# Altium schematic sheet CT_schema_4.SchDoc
size 313 x 185 mm
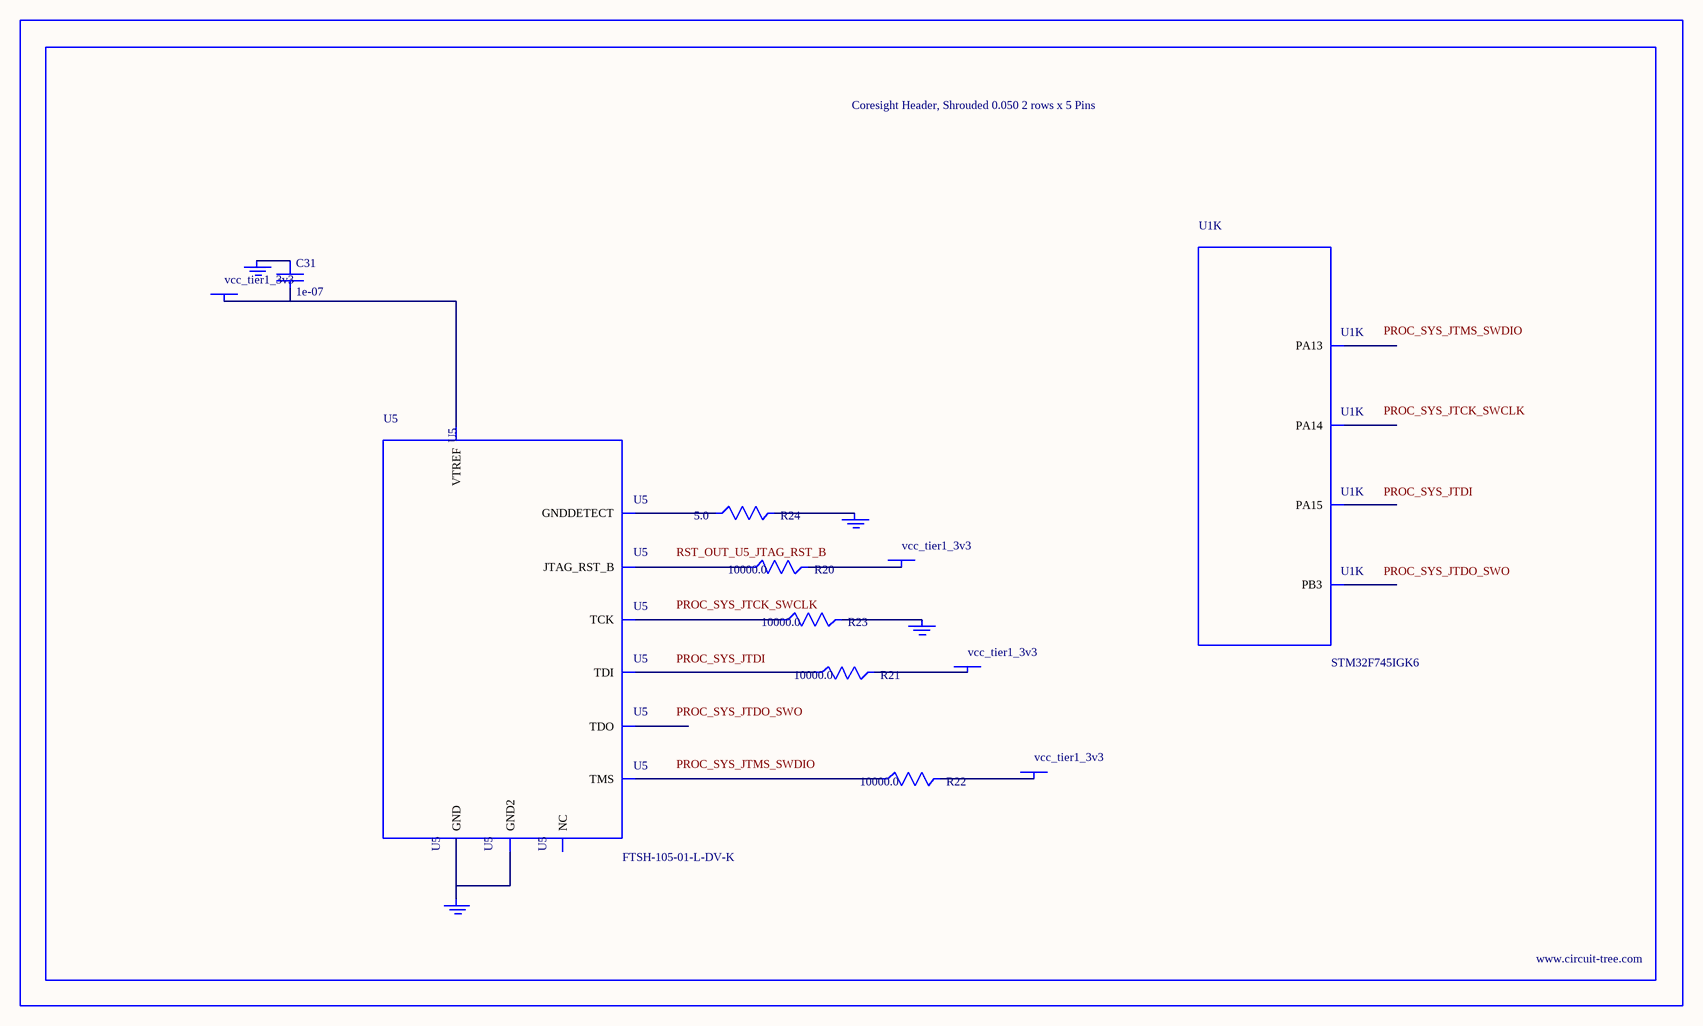
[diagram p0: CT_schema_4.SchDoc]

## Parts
BORDER3  (no value)
C31  1e-07  [C0402]
GND_INSTANCE_3_0  (no value)
GND_INSTANCE_3_1  (no value)
GND_INSTANCE_3_2  (no value)
GND_INSTANCE_3_3  (no value)
POWER_INSTANCE_3_0  vcc_tier1_3v3
POWER_INSTANCE_3_1  vcc_tier1_3v3
POWER_INSTANCE_3_2  vcc_tier1_3v3
POWER_INSTANCE_3_3  vcc_tier1_3v3
R20  10000.0  [R0603]
R21  10000.0  [R0603]
R22  10000.0  [R0603]
R23  10000.0  [R0603]
R24  5.0  [R0603]
U1  STM32F745IGK6  [UFBGA176_25]  (part K of 16)
U5  FTSH-105-01-L-DV-K  [SAMTEC_FTSH-105-01-L-DV-K]

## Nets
NetC31_1: C31.1 GND_INSTANCE_3_0.0(GND)
NetC31_2: C31.2 POWER_INSTANCE_3_0.0(PWR) U5.1(VTREF)
NetGND_INSTANCE_3_1_0: GND_INSTANCE_3_1.0(GND) R23.2
NetGND_INSTANCE_3_2_0: GND_INSTANCE_3_2.0(GND) R24.2
NetGND_INSTANCE_3_3_0: GND_INSTANCE_3_3.0(GND) U5.3(GND) U5.5(GND2)
NetPOWER_INSTANCE_3_1_0: POWER_INSTANCE_3_1.0(PWR) R22.2
NetPOWER_INSTANCE_3_2_0: POWER_INSTANCE_3_2.0(PWR) R21.2
NetPOWER_INSTANCE_3_3_0: POWER_INSTANCE_3_3.0(PWR) R20.2
NetR20_1: R20.1 U5.10(JTAG_RST_B)
NetR21_1: R21.1 U5.8(TDI)
NetR22_1: R22.1 U5.2(TMS)
NetR23_1: R23.1 U5.4(TCK)
NetR24_1: R24.1 U5.9(GNDDETECT)

Not connected (* = marked no-connect by the designer): U1 A10(PB3) A13(PA15) A14(PA14) A15(PA13); U5 6(TDO) 7(NC)

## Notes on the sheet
- Labels drawn without touching a wire or pin: PROC_SYS_JTCK_SWCLK, PROC_SYS_JTDI, PROC_SYS_JTDO_SWO, PROC_SYS_JTMS_SWDIO, RST_OUT_U5_JTAG_RST_B

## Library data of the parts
BORDER3 = BORDER_PAGE3
C31 = C0402C104K3RACTU
GND_INSTANCE_3_0-GND_INSTANCE_3_3 = GND
POWER_INSTANCE_3_0-POWER_INSTANCE_3_3 = PWR
R20-R23 = RC0603JR-0710KL
R24 = ERJ-3GEYJ5R1V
